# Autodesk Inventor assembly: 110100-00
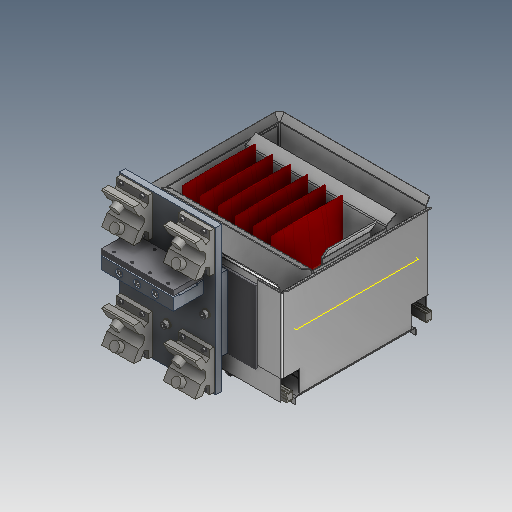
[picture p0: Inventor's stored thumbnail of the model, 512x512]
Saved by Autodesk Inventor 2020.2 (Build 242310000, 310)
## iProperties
Created: 2000-10
Part Number: 110100-00
Document SubType Name: Assembly
Designer: wymerj
Mass: 14269.6 g
Surface Area: 19861.8 cm^2
Volume: 4078.28 cm^3
Density: 3.49893 g/cm^3
Control State: 0
Master: False
Checked Out: False
Shininess: 0.0
Length Units: 11269
Angle Units: 11279
Time Units: 11290
Mass Units: 11283
Length Display Precision: 3
Angle Display Precision: 2
Compacted: True
Dimensions: 411,5x465,2x393 mm
Mass: 14,27 kg
DocNumber: ADSK-014244
Folder: 01 - Themengebiete\Simplification\01 - Packaging machine\
VDS_Category: 3D Komponenten
VDS_NumSchm: Autodesk
Density: 0.0
Volumn: 0.0
Area: 0.0
PropertySet Name: Model Information
Author: wymerj
Revision Number: -
Title: skid
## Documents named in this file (14)
- D:\07 - DEMODATEN\OTX 2019 - Dataset - UPDATE - Dez2019\Designs\07-Packing machine\110100-00.iam
- D:\07 - DEMODATEN\OTX 2019 - Dataset - UPDATE - Dez2019\Designs\07-Packing machine\500361.iam
- D:\07 - DEMODATEN\OTX 2019 - Dataset - UPDATE - Dez2019\Designs\07-Packing machine\500693.iam
- D:\07 - DEMODATEN\OTX 2019 - Dataset - UPDATE - Dez2019\Designs\07-Packing machine\Parts\ADSK-011742.ipt
- D:\07 - DEMODATEN\OTX 2019 - Dataset - UPDATE - Dez2019\Designs\07-Packing machine\Parts\ADSK-011668.ipt
- D:\07 - DEMODATEN\OTX 2019 - Dataset - UPDATE - Dez2019\Designs\07-Packing machine\Parts\ADSK-011673.ipt
- D:\07 - DEMODATEN\OTX 2019 - Dataset - UPDATE - Dez2019\Designs\07-Packing machine\500406.iam
- D:\07 - DEMODATEN\OTX 2019 - Dataset - UPDATE - Dez2019\Content Center Files\de-DE\DIN 125-1  B\DIN 125-1 - B 8,4.ipt
- D:\07 - DEMODATEN\OTX 2019 - Dataset - UPDATE - Dez2019\Content Center Files\de-DE\ISO 4762(2)\ISO 4762 - M8 x 25ISO.ipt
- D:\07 - DEMODATEN\OTX 2019 - Dataset - UPDATE - Dez2019\Content Center Files\de-DE\ISO 4762(2)\ISO 4762 - M8 x 80ISO.ipt
- D:\07 - DEMODATEN\OTX 2019 - Dataset - UPDATE - Dez2019\Content Center Files\de-DE\DIN 125-1  B\DIN 125-1 - B 4,3.ipt
- D:\07 - DEMODATEN\OTX 2019 - Dataset - UPDATE - Dez2019\Designs\07-Packing machine\Parts\ADSK-011759.ipt
- D:\07 - DEMODATEN\OTX 2019 - Dataset - UPDATE - Dez2019\Content Center Files\de-DE\ISO 4762(2)\ISO 4762 - M4 x 20ISO.ipt
- D:\07 - DEMODATEN\OTX 2019 - Dataset - UPDATE - Dez2019\Content Center Files\de-DE\ISO 4762(2)\ISO 4762 - M6 x 30ISO.ipt
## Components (59 placed, 13 different names)
1. 500361:1 [sub-assembly] — Mate:1, Mate:2, Mate:3, Insert:1, Mate:4, Insert:2, Mate:5, Insert:3, Mate:6, Insert:4, Mate:7, Passend:12, Passend:13, Passend:14
2. 500693:1 [sub-assembly] — Mate:1, Mate:2, Mate:3, Passend:66, Passend:67, Passend:68
3. ADSK-011742:1 — Insert:3, Mate:6
4. ADSK-011742:2 — Insert:1, Mate:4
5. ADSK-011742:3 — Insert:2, Mate:5
6. ADSK-011742:4 — Insert:4, Mate:7
7. ADSK-011668:1 — Passend:9, Passend:10, Passend:11, Passend:12, Passend:13, Passend:14, Passend:16, Passend:18, Passend:20, Passend:22, Passend:24, Passend:26, Passend:28, Passend:30, Passend:31, Passend:33
8. ADSK-011673:1 — Passend:9, Passend:10, Passend:11, Passend:32
9. 500406:1 [sub-assembly] — Passend:66, Passend:67, Passend:68
10. ADSK-011759:1 — Passend:31, Passend:32, Passend:33
11. ISO 4762 M4 x 20:1 — Passend:35
12. ISO 4762 M4 x 20:2 — Passend:37
13. ISO 4762 M4 x 20:3 — Passend:39
14. ISO 4762 M4 x 20:4 — Passend:41
15. ISO 4762 M4 x 20:5 — Passend:43
16. ISO 4762 M4 x 20:6 — Passend:45
17. ISO 4762 M4 x 20:7 — Passend:47
18. ISO 4762 M4 x 20:8 — Passend:49
19. ISO 4762 M4 x 20:9 — Passend:51
20. ISO 4762 M4 x 20:10 — Passend:53
21. ISO 4762 M4 x 20:11 — Passend:55
22. ISO 4762 M4 x 20:12 — Passend:57
23. ISO 4762 M4 x 20:13 — Passend:59
24. ISO 4762 M4 x 20:14 — Passend:61
25. ISO 4762 M4 x 20:15 — Passend:63
26. ISO 4762 M4 x 20:16 — Passend:65
27. DIN 125-1 B B 8,4:1
28. DIN 125-1 B B 8,4:3
29. DIN 125-1 B B 8,4:4
30. ISO 4762 M8 x 25:1
31. ISO 4762 M8 x 25:2
32. ISO 4762 M8 x 25:3
33. ISO 4762 M8 x 80:1
34. ISO 4762 M8 x 80:2
35. ISO 4762 M8 x 80:3
36. DIN 125-1 B B 4,3:1
37. DIN 125-1 B B 4,3:2 — Passend:51, Passend:53, Passend:55, Passend:57
38. DIN 125-1 B B 4,3:3
39. DIN 125-1 B B 4,3:4
40. DIN 125-1 B B 4,3:5
41. DIN 125-1 B B 4,3:6 — Passend:59, Passend:61, Passend:63, Passend:65
42. DIN 125-1 B B 4,3:7
43. DIN 125-1 B B 4,3:8
44. DIN 125-1 B B 4,3:9
45. DIN 125-1 B B 4,3:10
46. DIN 125-1 B B 4,3:11
47. DIN 125-1 B B 4,3:12 — Passend:43, Passend:45, Passend:47, Passend:49
48. DIN 125-1 B B 4,3:13
49. DIN 125-1 B B 4,3:14 — Passend:35, Passend:37, Passend:39, Passend:41
50. DIN 125-1 B B 4,3:15
51. DIN 125-1 B B 4,3:16
52. ISO 4762 M6 x 30:1 — Passend:16
53. ISO 4762 M6 x 30:2 — Passend:18
54. ISO 4762 M6 x 30:3 — Passend:20
55. ISO 4762 M6 x 30:4 — Passend:22
56. ISO 4762 M6 x 30:5 — Passend:24
57. ISO 4762 M6 x 30:6 — Passend:26
58. ISO 4762 M6 x 30:7 — Passend:28
59. ISO 4762 M6 x 30:8 — Passend:30
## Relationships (47: Mate 43, Insert 4)
- Mate:1: 500361:1 ↔ 500693:1
- Mate:2: 500361:1 ↔ 500693:1
- Mate:3: 500361:1 ↔ 500693:1
- Insert:1: 500361:1 ↔ ADSK-011742:2
- Mate:4: 500361:1 ↔ ADSK-011742:2
- Insert:2: 500361:1 ↔ ADSK-011742:3
- Mate:5: 500361:1 ↔ ADSK-011742:3
- Insert:3: 500361:1 ↔ ADSK-011742:1
- Mate:6: 500361:1 ↔ ADSK-011742:1
- Insert:4: 500361:1 ↔ ADSK-011742:4
- Mate:7: 500361:1 ↔ ADSK-011742:4
- Passend:9 [Mate]: ADSK-011668:1 ↔ ADSK-011673:1
- Passend:10 [Mate]: ADSK-011668:1 ↔ ADSK-011673:1
- Passend:11 [Mate]: ADSK-011668:1 ↔ ADSK-011673:1
- Passend:12 [Mate]: 500361:1 ↔ ADSK-011668:1
- Passend:13 [Mate]: 500361:1 ↔ ADSK-011668:1
- Passend:14 [Mate]: 500361:1 ↔ ADSK-011668:1
- Passend:16 [Mate]: ADSK-011668:1 ↔ ISO 4762 M6 x 30:1
- Passend:18 [Mate]: ADSK-011668:1 ↔ ISO 4762 M6 x 30:2
- Passend:20 [Mate]: ADSK-011668:1 ↔ ISO 4762 M6 x 30:3
- Passend:22 [Mate]: ADSK-011668:1 ↔ ISO 4762 M6 x 30:4
- Passend:24 [Mate]: ADSK-011668:1 ↔ ISO 4762 M6 x 30:5
- Passend:26 [Mate]: ADSK-011668:1 ↔ ISO 4762 M6 x 30:6
- Passend:28 [Mate]: ADSK-011668:1 ↔ ISO 4762 M6 x 30:7
- Passend:30 [Mate]: ADSK-011668:1 ↔ ISO 4762 M6 x 30:8
- Passend:31 [Mate]: ADSK-011668:1 ↔ ADSK-011759:1
- Passend:32 [Mate]: ADSK-011673:1 ↔ ADSK-011759:1
- Passend:33 [Mate]: ADSK-011668:1 ↔ ADSK-011759:1
- Passend:35 [Mate]: ISO 4762 M4 x 20:1 ↔ DIN 125-1 B B 4,3:14
- Passend:37 [Mate]: ISO 4762 M4 x 20:2 ↔ DIN 125-1 B B 4,3:14
- Passend:39 [Mate]: ISO 4762 M4 x 20:3 ↔ DIN 125-1 B B 4,3:14
- Passend:41 [Mate]: ISO 4762 M4 x 20:4 ↔ DIN 125-1 B B 4,3:14
- Passend:43 [Mate]: ISO 4762 M4 x 20:5 ↔ DIN 125-1 B B 4,3:12
- Passend:45 [Mate]: ISO 4762 M4 x 20:6 ↔ DIN 125-1 B B 4,3:12
- Passend:47 [Mate]: ISO 4762 M4 x 20:7 ↔ DIN 125-1 B B 4,3:12
- Passend:49 [Mate]: ISO 4762 M4 x 20:8 ↔ DIN 125-1 B B 4,3:12
- Passend:51 [Mate]: ISO 4762 M4 x 20:9 ↔ DIN 125-1 B B 4,3:2
- Passend:53 [Mate]: ISO 4762 M4 x 20:10 ↔ DIN 125-1 B B 4,3:2
- Passend:55 [Mate]: ISO 4762 M4 x 20:11 ↔ DIN 125-1 B B 4,3:2
- Passend:57 [Mate]: ISO 4762 M4 x 20:12 ↔ DIN 125-1 B B 4,3:2
- Passend:59 [Mate]: ISO 4762 M4 x 20:13 ↔ DIN 125-1 B B 4,3:6
- Passend:61 [Mate]: ISO 4762 M4 x 20:14 ↔ DIN 125-1 B B 4,3:6
- Passend:63 [Mate]: ISO 4762 M4 x 20:15 ↔ DIN 125-1 B B 4,3:6
- Passend:65 [Mate]: ISO 4762 M4 x 20:16 ↔ DIN 125-1 B B 4,3:6
- Passend:66 [Mate]: 500693:1 ↔ 500406:1
- Passend:67 [Mate]: 500693:1 ↔ 500406:1
- Passend:68 [Mate]: 500693:1 ↔ 500406:1
